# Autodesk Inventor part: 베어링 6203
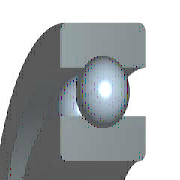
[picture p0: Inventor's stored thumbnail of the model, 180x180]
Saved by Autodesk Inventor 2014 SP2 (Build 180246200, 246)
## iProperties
IsCustomPart: 1
Created: 2015-09
Part Number: 베어링 6203
Material: 강철, 연강
Description: 깊은 그루브 볼 베어링
Document SubType Name: Modeling
Standard: KS B 2023
Standards Organization: KS
Language: ko-KR
Size Designation: 6203 - 17 x 40 x 12
Categories: <MemberInstance><Categories><Category DisplayName="샤프트 부품" InternalName="7f7aeb1f-a693-4053-b835-cee3144e0d98" Mnemonic="SHFT"><Category DisplayName="베어링" Inter
Density: 7.86 g/cm^3
Mass: 64.9809 g
Surface Area: 64.3582 cm^2
Volume: 8.26729 cm^3
Appearance: 강철
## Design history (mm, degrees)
sketch "스케치" dims "d0" = 5.98 (= -0.26 x WD + 0.26 x BD)
  geometry: L1 (3.01, 14.25)-(8.99, 14.25); L2 (6, 14.25)-(6, 11.26); L3 (6, 14.25)-(6, 17.24); L4 (3.778, 12.249)-(0, 12.249); L5 (0, 8.5)-(12, 8.5); L6 (3.778, 16.251)-(0, 16.251); L7 (0, 20)-(12, 20); L8 (12, 8.5)-(12, 12.249); L9 (8.222, 12.249)-(12, 12.249); L10 (8.222, 16.251)-(12, 16.251); L11 (12, 20)-(12, 16.251); L12 (-1.4, 0)-(8.4, 0) reference; L13 (0, -0.3)-(0, 5.3) reference
  constraints: 22 end point, 4 point on line, 2 collinear, 2 perpendicular, 2 symmetric about line, 1 midpoint, 1 parallel, 14 other
  dimensions: "d9" = 17 diameter of L5 L12 (= WD); "d11" = 40 diameter of L7 L12 (= BD); "d12" = 12 distance between parallel lines of L8 L13 (= KB); "d13" = 24.498 diameter of L9 L12 (= 0.326 x BD + 0.674 x WD)
revolve "본체" stored, may be unused: angle "d6" = 90 deg
revolve "볼" stored, may be unused: angle "d7" = 90 deg
pattern_circular "IDS_ARRAYBALL[SIMPL:T]" dims angle "d3" = 360 deg
body "Solid1"
fillet "모깎기1" dims "d1" = 0.6 (= KRS)
other parameters: "WD" = 17 [user parameter; used in 5 equation terms], "BD" = 40 [user parameter; used in 5 equation terms], "KB" = 12 [user parameter; used in 1 equation term], "KRS" = 0.6 [user parameter; used in 1 equation term], "d4" = 0, "d5" = 0, "d8" = 0, "d14" = 0, "d15" = 0, "BBA" = 0 [user parameter], "BC0" = 4750000 [user parameter], "BC" = 9560000 [user parameter], "WR" = 8.5 (= 0.5 x WD) [user parameter]
